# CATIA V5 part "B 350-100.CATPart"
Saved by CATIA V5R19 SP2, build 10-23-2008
Part number: B 350-100
Bounding box of the stored display mesh (mm): x -15.868 to 15.868, y -15.868 to 15.868, z 0 to 250
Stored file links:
  C:\Users\Bora\Desktop\3D Katı model\B serisi\B 350\B 350-100.CATPart
  C:\Program Files\Dassault Systemes\B19\intel_a\reffiles\standard\MetricThickPitch.txt
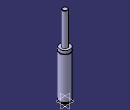
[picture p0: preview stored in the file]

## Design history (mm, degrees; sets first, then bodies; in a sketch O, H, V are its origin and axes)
Body1 (main body)
  Sketch1 on yz-plane, origin (0, 0, 0), H (0, 1, 0), V (0, 0, 1)
    point P1 (16, 138.5)
    point P4 (16, 136.5)
    point P7 (16, 138.5)
    point P8 (16, 136.5)
    point P9 (8, 249)
    point P11 (8, 249)
    line L1 (16, 138.5) -> (16, 148)
    line L2 (16, 7.5) -> (16, 136.5)
    line L3 (13.5, 7.5) -> (13.5, 4)
    arc A1 centre (16, 137.5) radius 1 from (16, 138.5) to (16, 136.5) ccw
    arc A2 centre (7, 249) radius 1 from (8, 249) to (7, 250) ccw
    line L4 (8, 249) -> (8, 148)
    line L5 (16, 0) -> (16, 4)
    line L6 (7, 250) -> (0, 250)
    point P15 (0, 250)
    line L7 (8, 148) -> (16, 148)
    line L8 (13.5, 7.5) -> (16, 7.5)
    line L9 (13.5, 4) -> (16, 4)
    line L10 (0, 0) -> (16, 0)
    coincidence: P15 V, P1 P7, P4 P8, P9 P11
    tangency: L6 A2
    horizontal: L7 H, L8 H, L9 H, L10 H
  Shaft1: profile Sketch1, axis Sketch1.V, angle 360
  Sketch2 on face of Shaft1 from Sketch1.L10, origin (0, 0, 0), H (1, 0, 0), V (0, -1, 0)
    point P1 (0, 0)
  Hole1: placed by Sketch2, at (0, 0, 0) direction (0, 0, 1), diameter 6.647, depth 7, threaded "M8", thread diameter 8, thread depth 7, pitch 1.25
